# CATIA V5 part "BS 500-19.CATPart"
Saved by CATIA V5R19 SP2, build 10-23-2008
Part number: BS 500-19
Bounding box of the stored display mesh (mm): x -18.951 to 18.951, y -18.952 to 18.952, z 0 to 68
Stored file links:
  C:\Users\Bora\Desktop\3D Katı model\BS serisi\BS 500\BS 500-19.CATPart
  C:\Program Files\Dassault Systemes\B19\intel_a\reffiles\standard\MetricThickPitch.txt
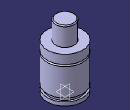
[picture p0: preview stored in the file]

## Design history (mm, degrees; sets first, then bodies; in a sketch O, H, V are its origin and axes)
Body1 (main body)
  Sketch1 on yz-plane, origin (0, 0, 0), H (0, 1, 0), V (0, 0, 1)
    point P1 (10, 67)
    point P3 (10, 67)
    point P5 (19, 38.5)
    point P6 (19, 36.5)
    point P9 (19, 38.5)
    point P14 (19, 36.5)
    line L1 (10, 67) -> (10, 48)
    arc A1 centre (9, 67) radius 1 from (10, 67) to (9, 68) ccw
    arc A2 centre (19, 37.5) radius 1 from (19, 38.5) to (19, 36.5) ccw
    line L2 (19, 0) -> (19, 4)
    line L3 (19, 38.5) -> (19, 48)
    line L4 (17, 7.5) -> (17, 4)
    line L5 (19, 7.5) -> (19, 36.5)
    line L6 (9, 68) -> (0, 68)
    point P15 (0, 68)
    line L7 (10, 48) -> (19, 48)
    line L8 (0, 0) -> (19, 0)
    line L9 (17, 7.5) -> (19, 7.5)
    line L10 (17, 4) -> (19, 4)
    tangency: L6 A1
    coincidence: P15 V, P1 P3, P5 P9, P6 P14
    horizontal: L7 H, L8 H, L9 H, L10 H
  Shaft1: profile Sketch1, axis Sketch1.V, angle 360
  Sketch2 on face of Shaft1 from Sketch1.L8, origin (0, 0, 0), H (1, 0, 0), V (0, -1, 0)
    point P1 (0, 0)
  Hole1: placed by Sketch2, at (0, 0, 0) direction (0, 0, 1), diameter 6.647, depth 4, threaded "M8", thread diameter 8, thread depth 4, pitch 1.25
